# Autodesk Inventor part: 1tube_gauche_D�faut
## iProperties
Created: 2011-01
Part Number: 1tube_gauche_D�faut
Document SubType Name: Modeling
Designer: eric
Density: 1 g/cm^3
Mass: 24.5987 g
Surface Area: 493.796 cm^2
Volume: 24.5987 cm^3
Author: eric
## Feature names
1. Base1
